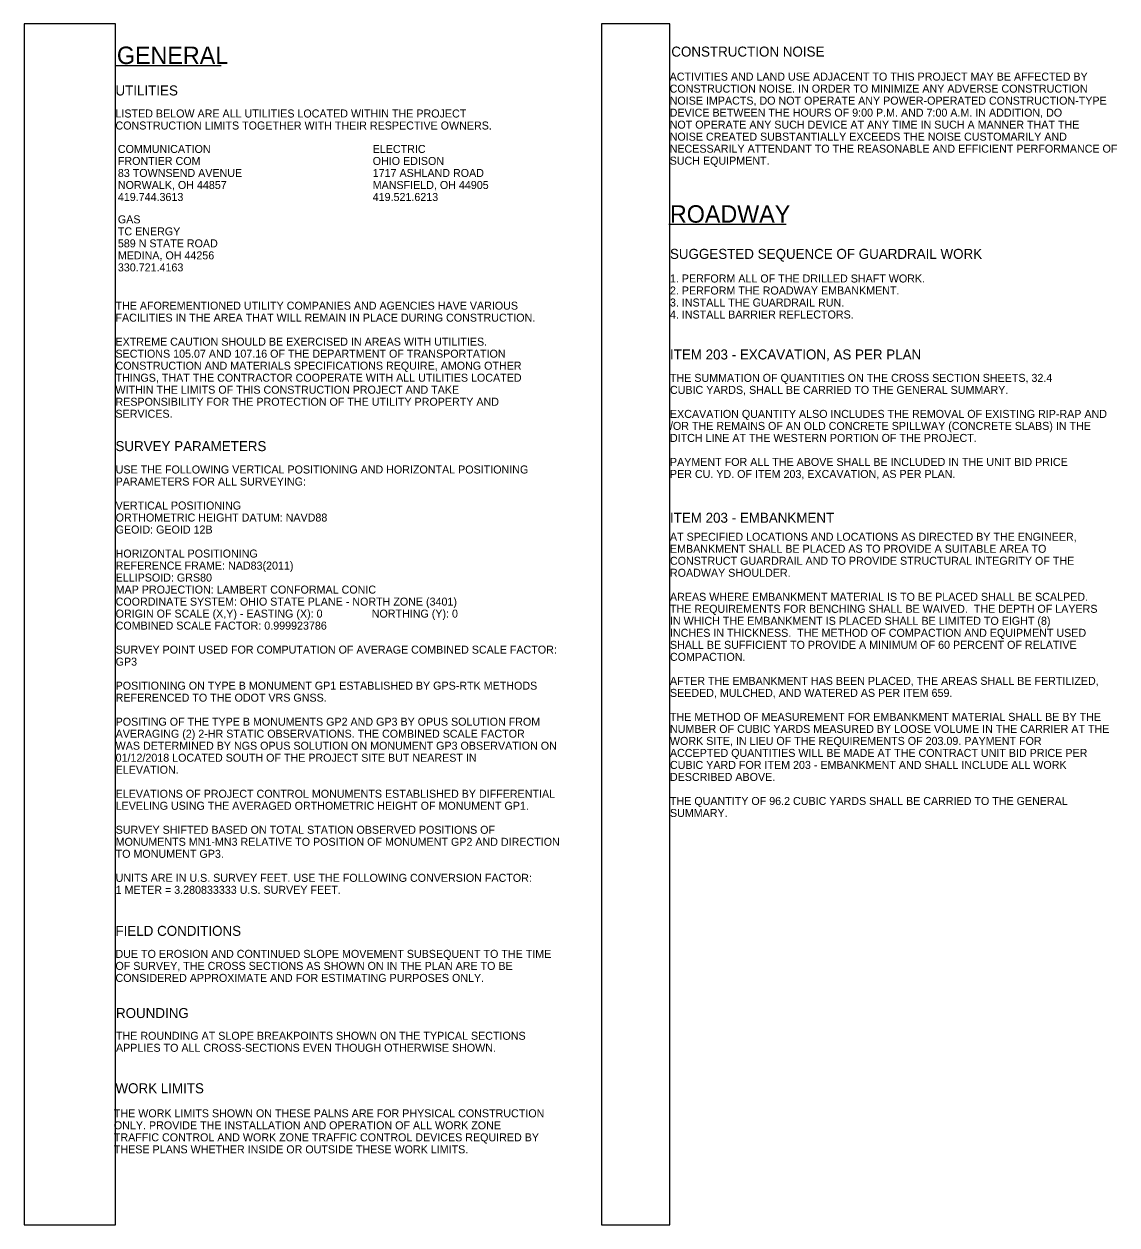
# Model space of a CAD drawing. Extents: x -9.7 to 42.8, y 0 to 45.4.
# Drawn here: x 1.5 to 20.62, y 24.42 to 45.42 of the extents above; entities that cross this region are included whole.
import ezdxf

# ---------------------------------------------------------------- set-up
doc = ezdxf.new("R2010")
doc.units = 0
for name, color, linetype in [('Default', 7, 'Continuous'), ('SC_Scratch1', 7, 'Continuous'), ('TX_P_1', 7, 'Continuous')]:
    doc.layers.add(name, color=color, linetype=linetype)

msp = doc.modelspace()

# ---------------------------------------------------------------- linework, layer by layer
at = {"layer": 'Default'}
for p, q in [((3.107, 44.696), (4.948, 44.696)), ((12.781, 41.922), (14.836, 41.922))]:
    msp.add_line(p, q, dxfattribs=at)
at = {"layer": 'SC_Scratch1'}
for p, q in [((3.1, 45.42), (1.5, 45.42)), ((1.5, 45.42), (1.5, 24.42)), ((3.1, 24.42), (3.1, 45.42)), ((11.6, 45.42), (11.6, 24.42)), ((12.8, 45.42), (11.6, 45.42)), ((12.8, 24.42), (12.8, 45.42)), ((1.5, 24.42), (3.1, 24.42)), ((11.6, 24.42), (12.8, 24.42))]:
    msp.add_line(p, q, dxfattribs=at)

# ---------------------------------------------------------------- texts
at = {"layer": 'TX_P_1'}
for s, height, p in [('GENERAL', 0.3047, (3.125, 44.72)), ('CONSTRUCTION NOISE', 0.175, (12.824, 44.85)), ('ACTIVITIES AND LAND USE ADJACENT TO THIS PROJECT MAY BE AFFECTED BY ', 0.14, (12.795, 44.43)), ('UTILITIES', 0.175, (3.1, 44.17)), ('CONSTRUCTION NOISE. IN ORDER TO MINIMIZE ANY ADVERSE CONSTRUCTION ', 0.14, (12.795, 44.22)), ('NOISE IMPACTS, DO NOT OPERATE ANY POWER-OPERATED CONSTRUCTION-TYPE ', 0.14, (12.795, 44.01)), ('LISTED BELOW ARE ALL UTILITIES LOCATED WITHIN THE PROJECT ', 0.14, (3.1, 43.785)), ('DEVICE BETWEEN THE HOURS OF 9:00 P.M. AND 7:00 A.M. IN ADDITION, DO ', 0.14, (12.795, 43.8)), ('CONSTRUCTION LIMITS TOGETHER WITH THEIR RESPECTIVE OWNERS.', 0.14, (3.1, 43.575)), ('NOT OPERATE ANY SUCH DEVICE AT ANY TIME IN SUCH A MANNER THAT THE ', 0.14, (12.795, 43.59)), ('NOISE CREATED SUBSTANTIALLY EXCEEDS THE NOISE CUSTOMARILY AND ', 0.14, (12.795, 43.38)), ('COMMUNICATION', 0.14, (3.142, 43.165)), ('ELECTRIC', 0.14, (7.6, 43.165)), ('NECESSARILY ATTENDANT TO THE REASONABLE AND EFFICIENT PERFORMANCE OF ', 0.14, (12.795, 43.17)), ('FRONTIER COM', 0.14, (3.142, 42.955)), ('OHIO EDISON', 0.14, (7.6, 42.955)), ('SUCH EQUIPMENT.', 0.14, (12.795, 42.96)), ('83 TOWNSEND AVENUE', 0.14, (3.142, 42.745)), ('1717 ASHLAND ROAD', 0.14, (7.6, 42.745)), ('NORWALK, OH 44857', 0.14, (3.142, 42.535)), ('MANSFIELD, OH 44905', 0.14, (7.6, 42.535)), ('419.744.3613', 0.14, (3.142, 42.325)), ('419.521.6213', 0.14, (7.6, 42.325)), ('ROADWAY', 0.3047, (12.8, 41.946)), ('GAS', 0.14, (3.142, 41.934)), ('TC ENERGY ', 0.14, (3.142, 41.724)), ('589 N STATE ROAD', 0.14, (3.142, 41.514)), ('MEDINA, OH 44256', 0.14, (3.142, 41.304)), ('SUGGESTED SEQUENCE OF GUARDRAIL WORK', 0.175, (12.8, 41.313)), ('330.721.4163', 0.14, (3.142, 41.094)), ('1. PERFORM ALL OF THE DRILLED SHAFT WORK. ', 0.14, (12.8, 40.9)), ('2. PERFORM THE ROADWAY EMBANKMENT.  ', 0.14, (12.8, 40.69)), ('THE AFOREMENTIONED UTILITY COMPANIES AND AGENCIES HAVE VARIOUS ', 0.14, (3.1, 40.425)), ('3. INSTALL THE GUARDRAIL RUN. ', 0.14, (12.8, 40.48)), ('FACILITIES IN THE AREA THAT WILL REMAIN IN PLACE DURING CONSTRUCTION.', 0.14, (3.1, 40.215)), ('4. INSTALL BARRIER REFLECTORS.', 0.14, (12.8, 40.27)), ('EXTREME CAUTION SHOULD BE EXERCISED IN AREAS WITH UTILITIES.  ', 0.14, (3.1, 39.795)), ('SECTIONS 105.07 AND 107.16 OF THE DEPARTMENT OF TRANSPORTATION ', 0.14, (3.1, 39.585)), ('ITEM 203 - EXCAVATION, AS PER PLAN', 0.175, (12.8, 39.554)), ('CONSTRUCTION AND MATERIALS SPECIFICATIONS REQUIRE, AMONG OTHER ', 0.14, (3.1, 39.375)), ('THINGS, THAT THE CONTRACTOR COOPERATE WITH ALL UTILITIES LOCATED ', 0.14, (3.1, 39.165)), ('THE SUMMATION OF QUANTITIES ON THE CROSS SECTION SHEETS, 32.4 ', 0.14, (12.8, 39.162)), ('WITHIN THE LIMITS OF THIS CONSTRUCTION PROJECT AND TAKE ', 0.14, (3.1, 38.955)), ('CUBIC YARDS, SHALL BE CARRIED TO THE GENERAL SUMMARY.', 0.14, (12.8, 38.952)), ('RESPONSIBILITY FOR THE PROTECTION OF THE UTILITY PROPERTY AND ', 0.14, (3.1, 38.745)), ('SERVICES.', 0.14, (3.1, 38.535)), ('EXCAVATION QUANTITY ALSO INCLUDES THE REMOVAL OF EXISTING RIP-RAP AND', 0.14, (12.8, 38.532)), ('/OR THE REMAINS OF AN OLD CONCRETE SPILLWAY (CONCRETE SLABS) IN THE  ', 0.14, (12.8, 38.322)), ('DITCH LINE AT THE WESTERN PORTION OF THE PROJECT.  ', 0.14, (12.8, 38.112)), ('SURVEY PARAMETERS', 0.175, (3.1, 37.951)), ('PAYMENT FOR ALL THE ABOVE SHALL BE INCLUDED IN THE UNIT BID PRICE ', 0.14, (12.8, 37.692)), ('USE THE FOLLOWING VERTICAL POSITIONING AND HORIZONTAL POSITIONING ', 0.14, (3.103, 37.56)), ('PER CU. YD. OF ITEM 203, EXCAVATION, AS PER PLAN.', 0.14, (12.8, 37.482)), ('PARAMETERS FOR ALL SURVEYING:', 0.14, (3.103, 37.35)), ('VERTICAL POSITIONING ', 0.14, (3.103, 36.93)), ('ORTHOMETRIC HEIGHT DATUM: NAVD88 ', 0.14, (3.103, 36.72)), ('ITEM 203 - EMBANKMENT', 0.175, (12.8, 36.699)), ('GEOID: GEOID 12B', 0.14, (3.103, 36.51)), ('AT SPECIFIED LOCATIONS AND LOCATIONS AS DIRECTED BY THE ENGINEER, ', 0.14, (12.8, 36.384)), ('HORIZONTAL POSITIONING ', 0.14, (3.103, 36.09)), ('EMBANKMENT SHALL BE PLACED AS TO PROVIDE A SUITABLE AREA TO ', 0.14, (12.8, 36.174)), ('REFERENCE FRAME: NAD83(2011) ', 0.14, (3.103, 35.88)), ('CONSTRUCT GUARDRAIL AND TO PROVIDE STRUCTURAL INTEGRITY OF THE ', 0.14, (12.8, 35.964)), ('ELLIPSOID: GRS80 ', 0.14, (3.103, 35.67)), ('ROADWAY SHOULDER.', 0.14, (12.8, 35.754)), ('MAP PROJECTION: LAMBERT CONFORMAL CONIC ', 0.14, (3.103, 35.46)), ('COORDINATE SYSTEM: OHIO STATE PLANE - NORTH ZONE (3401)', 0.14, (3.103, 35.25)), ('AREAS WHERE EMBANKMENT MATERIAL IS TO BE PLACED SHALL BE SCALPED. ', 0.14, (12.8, 35.334)), ('ORIGIN OF SCALE (X,Y) - EASTING (X): 0 ', 0.14, (3.103, 35.04)), ('NORTHING (Y): 0', 0.14, (7.583, 35.04)), ('THE REQUIREMENTS FOR BENCHING SHALL BE WAIVED.  THE DEPTH OF LAYERS ', 0.14, (12.8, 35.124)), ('COMBINED SCALE FACTOR: 0.999923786', 0.14, (3.103, 34.83)), ('IN WHICH THE EMBANKMENT IS PLACED SHALL BE LIMITED TO EIGHT (8) ', 0.14, (12.8, 34.914)), ('INCHES IN THICKNESS.  THE METHOD OF COMPACTION AND EQUIPMENT USED ', 0.14, (12.8, 34.704)), ('SURVEY POINT USED FOR COMPUTATION OF AVERAGE COMBINED SCALE FACTOR: ', 0.14, (3.103, 34.41)), ('SHALL BE SUFFICIENT TO PROVIDE A MINIMUM OF 60 PERCENT OF RELATIVE ', 0.14, (12.8, 34.494)), ('GP3', 0.14, (3.103, 34.2)), ('COMPACTION.', 0.14, (12.8, 34.284)), ('POSITIONING ON TYPE B MONUMENT GP1 ESTABLISHED BY GPS-RTK METHODS ', 0.14, (3.103, 33.78)), ('AFTER THE EMBANKMENT HAS BEEN PLACED, THE AREAS SHALL BE FERTILIZED, ', 0.14, (12.8, 33.864)), ('REFERENCED TO THE ODOT VRS GNSS.', 0.14, (3.103, 33.57)), ('SEEDED, MULCHED, AND WATERED AS PER ITEM 659. ', 0.14, (12.8, 33.654)), ('POSITING OF THE TYPE B MONUMENTS GP2 AND GP3 BY OPUS SOLUTION FROM ', 0.14, (3.103, 33.15)), ('THE METHOD OF MEASUREMENT FOR EMBANKMENT MATERIAL SHALL BE BY THE ', 0.14, (12.8, 33.234)), ('AVERAGING (2) 2-HR STATIC OBSERVATIONS. THE COMBINED SCALE FACTOR ', 0.14, (3.103, 32.94)), ('NUMBER OF CUBIC YARDS MEASURED BY LOOSE VOLUME IN THE CARRIER AT THE ', 0.14, (12.8, 33.024)), ('WAS DETERMINED BY NGS OPUS SOLUTION ON MONUMENT GP3 OBSERVATION ON ', 0.14, (3.103, 32.73)), ('WORK SITE, IN LIEU OF THE REQUIREMENTS OF 203.09. PAYMENT FOR ', 0.14, (12.8, 32.814)), ('01/12/2018 LOCATED SOUTH OF THE PROJECT SITE BUT NEAREST IN ', 0.14, (3.103, 32.52)), ('ACCEPTED QUANTITIES WILL BE MADE AT THE CONTRACT UNIT BID PRICE PER ', 0.14, (12.8, 32.604)), ('ELEVATION.', 0.14, (3.103, 32.31)), ('CUBIC YARD FOR ITEM 203 - EMBANKMENT AND SHALL INCLUDE ALL WORK ', 0.14, (12.8, 32.394)), ('DESCRIBED ABOVE.', 0.14, (12.8, 32.184)), ('ELEVATIONS OF PROJECT CONTROL MONUMENTS ESTABLISHED BY DIFFERENTIAL ', 0.14, (3.103, 31.89)), ('LEVELING USING THE AVERAGED ORTHOMETRIC HEIGHT OF MONUMENT GP1.', 0.14, (3.103, 31.68)), ('THE QUANTITY OF 96.2 CUBIC YARDS SHALL BE CARRIED TO THE GENERAL ', 0.14, (12.8, 31.764)), ('SUMMARY.', 0.14, (12.8, 31.554)), ('SURVEY SHIFTED BASED ON TOTAL STATION OBSERVED POSITIONS OF ', 0.14, (3.103, 31.26)), ('MONUMENTS MN1-MN3 RELATIVE TO POSITION OF MONUMENT GP2 AND DIRECTION ', 0.14, (3.103, 31.05)), ('TO MONUMENT GP3.', 0.14, (3.103, 30.84)), ('UNITS ARE IN U.S. SURVEY FEET. USE THE FOLLOWING CONVERSION FACTOR: ', 0.14, (3.103, 30.42)), ('1 METER = 3.280833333 U.S. SURVEY FEET. ', 0.14, (3.103, 30.21)), ('FIELD CONDITIONS', 0.175, (3.1, 29.475)), ('DUE TO EROSION AND CONTINUED SLOPE MOVEMENT SUBSEQUENT TO THE TIME ', 0.14, (3.1, 29.09)), ('OF SURVEY, THE CROSS SECTIONS AS SHOWN ON IN THE PLAN ARE TO BE ', 0.14, (3.1, 28.88)), ('CONSIDERED APPROXIMATE AND FOR ESTIMATING PURPOSES ONLY.', 0.14, (3.1, 28.67)), ('ROUNDING', 0.175, (3.109, 28.038)), ('THE ROUNDING AT SLOPE BREAKPOINTS SHOWN ON THE TYPICAL SECTIONS ', 0.14, (3.109, 27.658)), ('APPLIES TO ALL CROSS-SECTIONS EVEN THOUGH OTHERWISE SHOWN.', 0.14, (3.109, 27.448)), ('WORK LIMITS', 0.175, (3.1, 26.723)), ('THE WORK LIMITS SHOWN ON THESE PALNS ARE FOR PHYSICAL CONSTRUCTION ', 0.14, (3.072, 26.302)), ('ONLY. PROVIDE THE INSTALLATION AND OPERATION OF ALL WORK ZONE ', 0.14, (3.072, 26.092)), ('TRAFFIC CONTROL AND WORK ZONE TRAFFIC CONTROL DEVICES REQUIRED BY ', 0.14, (3.072, 25.882)), ('THESE PLANS WHETHER INSIDE OR OUTSIDE THESE WORK LIMITS.', 0.14, (3.072, 25.672))]:
    msp.add_text(s, height=height, dxfattribs=at).set_placement(p)

doc.saveas('drawing.dxf')
